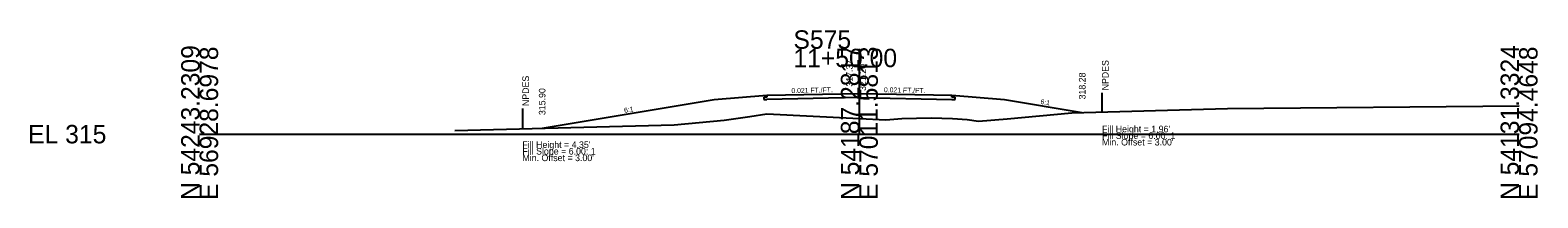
# Model space of a CAD drawing. Extents: x 10119 to 10347, y 94341 to 98867.
# Drawn here: x 10118.6 to 10347.2, y 95341.1 to 95366.6 of the extents above; entities that cross this region are included whole.
import ezdxf

# ---------------------------------------------------------------- set-up
doc = ezdxf.new("R2010")
doc.units = 0
for name, color, linetype in [('Level 10', 7, 'Continuous'), ('Level 11', 7, 'Continuous'), ('Level 12', 7, 'Continuous'), ('Level 32', 7, 'Continuous'), ('Level 33', 7, 'Continuous'), ('Level 50', 7, 'Continuous'), ('Level 55', 7, 'Continuous'), ('Level 59', 7, 'Continuous'), ('Level 6', 7, 'Continuous'), ('Level 60', 7, 'Continuous'), ('Level 63', 7, 'Continuous'), ('Level 7', 7, 'Continuous')]:
    doc.layers.add(name, color=color, linetype=linetype)

msp = doc.modelspace()

# ---------------------------------------------------------------- linework, layer by layer
at = {"layer": 'Level 11'}
for p, q in [((10230.31, 95356.43), (10229.81, 95356.42)), ((10229.81, 95356.42), (10229.81, 95356.08)), ((10229.81, 95356.08), (10230.31, 95356.09)), ((10230.31, 95356.72), (10230.31, 95356.43)), ((10258.31, 95356.43), (10258.31, 95356.72)), ((10258.81, 95356.42), (10258.31, 95356.43)), ((10258.31, 95356.09), (10258.81, 95356.08)), ((10258.81, 95356.08), (10258.81, 95356.42))]:
    msp.add_line(p, q, dxfattribs=at)
at = {"layer": 'Level 12'}
for q in [(10230.31, 95356.09), (10258.31, 95356.09)]:
    msp.add_line((10244.31, 95356.38), q, dxfattribs=at)
at = {"layer": 'Level 55'}
for p, q in [((10281.09, 95354.09), (10281.09, 95357.09)), ((10193.23, 95354.71), (10193.23, 95351.71))]:
    msp.add_line(p, q, dxfattribs=at)
at = {"layer": 'Level 59'}
for p, q in [((10230.31, 95356.72), (10244.31, 95357.01)), ((10244.31, 95357.01), (10258.31, 95356.72))]:
    msp.add_line(p, q, dxfattribs=at)
at = {"layer": 'Level 6'}
for p, q in [((10222.31, 95356.06), (10230.31, 95356.72)), ((10258.31, 95356.72), (10266.31, 95356.06))]:
    msp.add_line(p, q, dxfattribs=at)
at = {"layer": 'Level 60'}
for p, q in [((10223.8, 95352.93), (10227.71, 95353.49)), ((10227.71, 95353.49), (10230.27, 95353.9)), ((10230.27, 95353.9), (10244.31, 95353.18)), ((10266.73, 95353.14), (10276.5, 95354.05)), ((10276.5, 95354.05), (10300.09, 95354.7)), ((10300.09, 95354.7), (10344.31, 95355.14)), ((10183, 95351.38), (10216.24, 95352.21)), ((10216.24, 95352.21), (10223.8, 95352.93)), ((10244.31, 95353.18), (10248.3, 95352.97)), ((10248.3, 95352.97), (10250.75, 95353.19)), ((10250.75, 95353.19), (10255.17, 95353.27)), ((10255.17, 95353.27), (10258.43, 95353.2)), ((10258.43, 95353.2), (10260.67, 95353.06)), ((10260.67, 95353.06), (10262.39, 95352.77)), ((10262.39, 95352.77), (10266.73, 95353.14))]:
    msp.add_line(p, q, dxfattribs=at)
at = {"layer": 'Level 63'}
for p, q in [((10244.31, 95350.81), (10244.31, 95363.79)), ((10144.31, 95350.81), (10244.31, 95350.81)), ((10244.31, 95350.81), (10344.31, 95350.81))]:
    msp.add_line(p, q, dxfattribs=at)
at = {"layer": 'Level 7'}
for p, q in [((10196.23, 95351.71), (10222.31, 95356.06)), ((10266.31, 95356.06), (10278.09, 95354.09))]:
    msp.add_line(p, q, dxfattribs=at)

# ---------------------------------------------------------------- texts
at = {"layer": 'Level 10'}
msp.add_text('317.37', height=1, rotation=90, dxfattribs=at).set_placement((10243.31, 95358.03))
at = {"layer": 'Level 32'}
for s, rotation, p in [('0.021 FT./FT.', 1.1916, (10234.02, 95357.05)), ('0.021 FT./FT.', 358.8084, (10248.03, 95357.19)), ('6:1', 350.5377, (10271.72, 95355.41)), ('6:1', 9.4623, (10208.71, 95354.04))]:
    msp.add_text(s, height=0.75, rotation=rotation, dxfattribs=at).set_placement(p)
at = {"layer": 'Level 33'}
for s, p in [('318.28', (10278.59, 95356.09)), ('315.90', (10196.73, 95353.71))]:
    msp.add_text(s, height=1, rotation=90, dxfattribs=at).set_placement(p)
at = {"layer": 'Level 50'}
for p in [(10282.09, 95357.09), (10194.23, 95354.71)]:
    msp.add_text(' NPDES', height=1, rotation=90, dxfattribs=at).set_placement(p)
for s, p in [("Fill Height = 1.96' ", (10281.09, 95351.09)), ('Fill Slope = 6.00: 1', (10281.09, 95350.09)), ("Fill Height = 4.35' ", (10193.23, 95348.71)), ('Fill Slope = 6.00: 1', (10193.23, 95347.71)), ("Min. Offset = 3.00' ", (10281.09, 95349.09)), ("Min. Offset = 3.00' ", (10193.23, 95346.71))]:
    msp.add_text(s, height=1, dxfattribs=at).set_placement(p)
at = {"layer": 'Level 59'}
msp.add_text(' 321.20', height=1, rotation=90, dxfattribs=at).set_placement((10245.31, 95357.01))
at = {"layer": 'Level 63'}
for s, p in [('S575', (10234.32, 95363.79)), ('11+50.00', (10234.31, 95360.99)), ('EL 315', (10118.31, 95349.41))]:
    msp.add_text(s, height=2.8, dxfattribs=at).set_placement(p)
for s, p in [('N 54243.2309', (10144.31, 95340.81)), ('E 56928.6978', (10147.11, 95340.81)), ('N 54187.2817', (10244.31, 95340.81)), ('E 57011.5813', (10247.11, 95340.81)), ('N 54131.3324', (10344.31, 95340.81)), ('E 57094.4648', (10347.11, 95340.81))]:
    msp.add_text(s, height=2.8, rotation=90, dxfattribs=at).set_placement(p)

doc.saveas('drawing.dxf')
